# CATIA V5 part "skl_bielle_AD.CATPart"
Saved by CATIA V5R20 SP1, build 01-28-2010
Part number: skl_bielle_AD
Publications: "Droite.4", "Droite.5", "Droite.6", "Cercle.2", "D", "A", "Plan.1"
Bounding box of the stored display mesh (mm): x -54.998 to 44.954, y 0 to 20, z -9.997 to 76.688
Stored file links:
  C:\Users\Matthieu\Desktop\IAO_2012_mcamard_Catia\skl_bielle_AD.CATPart
  C:\Users\Matthieu\Desktop\IAO_Artobolevsky\skl_Artoboloevsky_786.CATProduct
  C:\Users\Matthieu\Desktop\IAO_2012_mcamard_Catia\skl_bati.CATPart
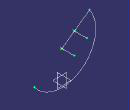
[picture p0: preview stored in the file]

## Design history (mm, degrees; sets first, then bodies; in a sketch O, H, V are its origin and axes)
Set1
  Line1: type PtPt, FirstPoint Point1, SecondPoint Point2, Start 30
  Line2: type PtDir, RefPoint Point1, Direction Plane1, Start 0, End 20
  Line3: type PtDir, RefPoint Point2, Direction Plane1, Start 0, End 20
  Circle1: type CtrPt, Start 0, End -180, Center Point2, Support zx-plane, RefPoint vertex of Line1
Set2
  Point1 "D": linked copy from another document
  Point2 "A": linked copy from another document
  Plane1: linked copy from another document
Body1 (main body)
